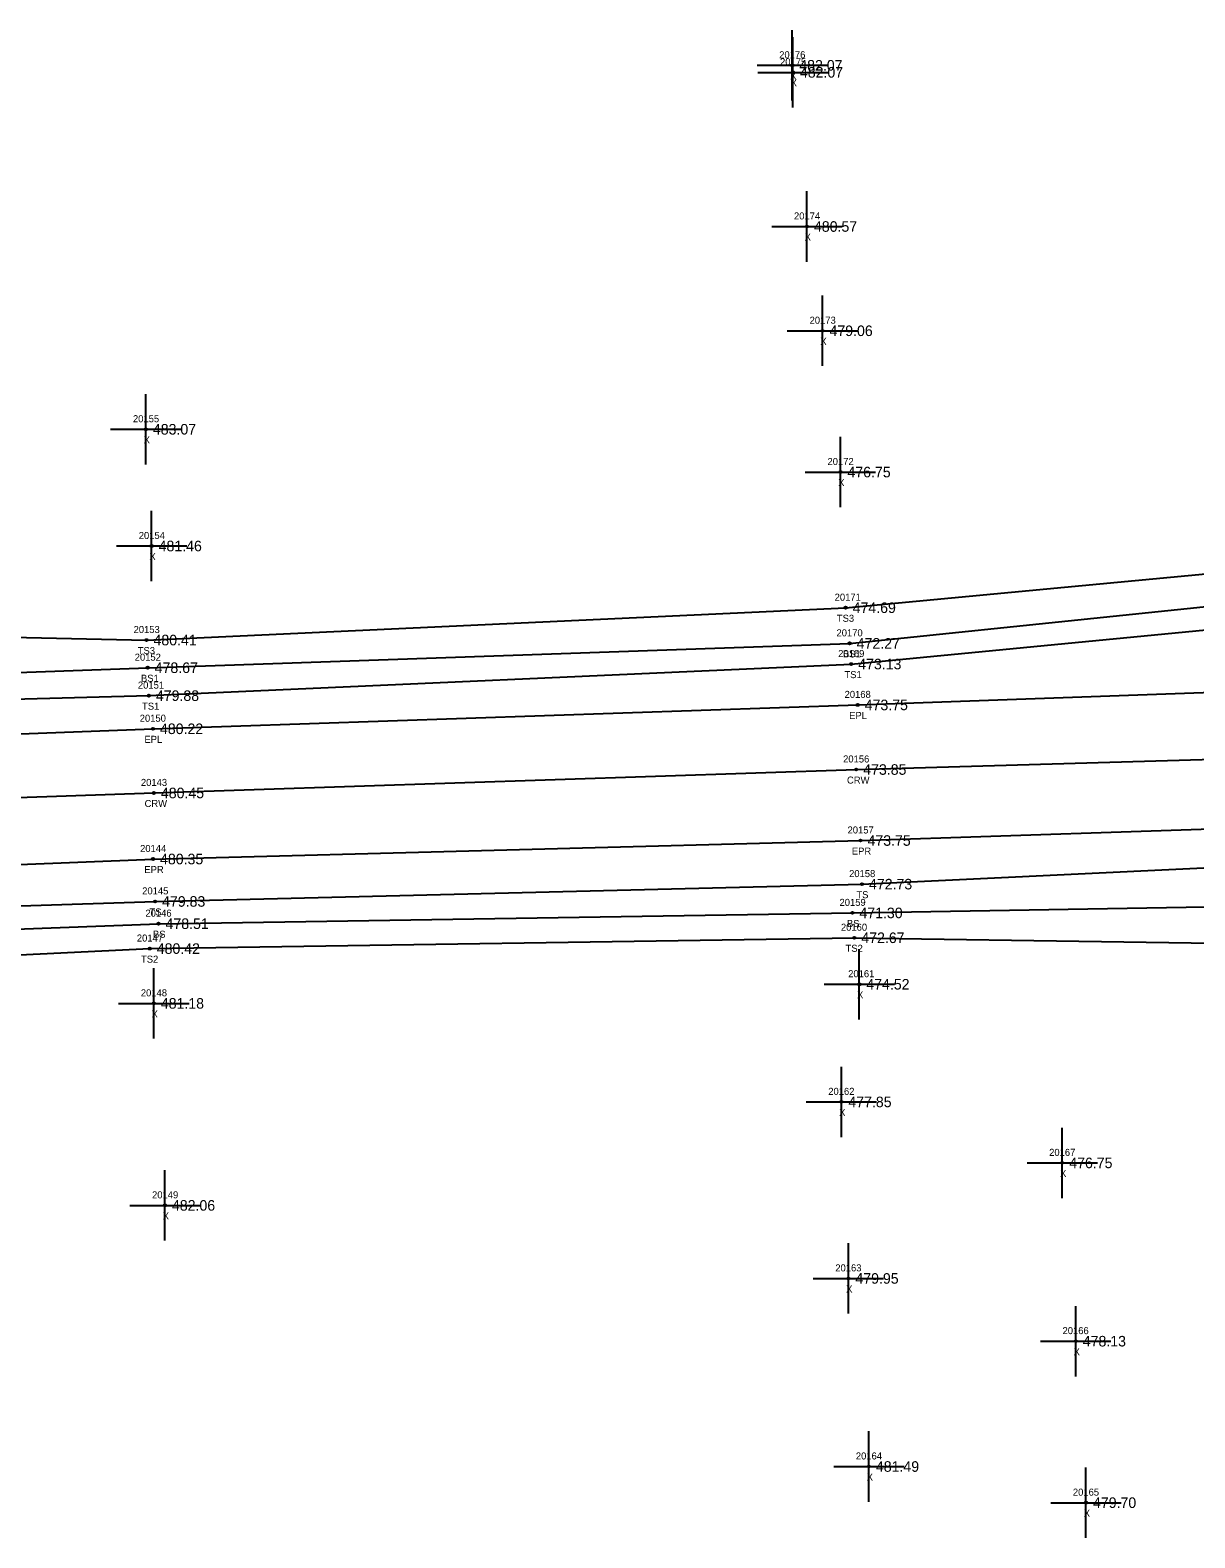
# Model space of a CAD drawing. Extents: x 1785066 to 1786589, y 770293 to 771312.
# Drawn here: x 1785562.6 to 1785728.1, y 770741.5 to 770955.7 of the extents above; entities that cross this region are included whole.
import ezdxf

# ---------------------------------------------------------------- set-up
doc = ezdxf.new("R2010")
doc.units = 0
for name, color, linetype in [('RD_DTM_BkLn1', 7, 'Continuous'), ('RD_DTM_BkLn2', 7, 'Continuous'), ('RD_DTM_BkLn_txCode', 7, 'Continuous'), ('RD_EX_Misc', 7, 'Continuous'), ('RD_EX_Misc_txCode', 7, 'Continuous'), ('RD_EX_Road', 7, 'Continuous'), ('RD_EX_Road_txCode', 7, 'Continuous'), ('RD_EX_TX_Misc_ELEV', 7, 'Continuous'), ('RD_EX_TX_Road_ELEV', 7, 'Continuous'), ('RD_HC_Survey_ELEV', 7, 'Continuous'), ('RD_HC_Survey_txCode', 7, 'Continuous'), ('RD_SMD_Locator', 7, 'Continuous')]:
    doc.layers.add(name, color=color, linetype=linetype)

msp = doc.modelspace()

# ---------------------------------------------------------------- linework, layer by layer
at = {"layer": 'RD_DTM_BkLn1'}
msp.add_lwpolyline([(1785082.06, 770851.29), (1785131.3, 770843.85), (1785181.17, 770839.05), (1785231.06, 770837.12), (1785280.99, 770837.06), (1785330.97, 770838.45), (1785380.81, 770840.43), (1785480.56, 770843.94), (1785580.22, 770847.33), (1785679.99, 770850.66), (1785779.91, 770853.54)], dxfattribs=at)
at = {"layer": 'RD_DTM_BkLn2'}
for points in [[(1785219, 770887.48), (1785221.61, 770869.17), (1785226.44, 770862.44), (1785230.83, 770863.64), (1785281.61, 770865.88), (1785330.18, 770866.95), (1785380.62, 770873.53), (1785481.03, 770871.22), (1785579.17, 770869.06), (1785678.49, 770873.66), (1785753.25, 770880.69), (1785777.57, 770887.66), (1785796.72, 770894.6)], [(1785221.18, 770856.06), (1785231.29, 770855.17), (1785280.9, 770855.5), (1785330.48, 770855.32), (1785380.39, 770857.59), (1785481.4, 770861.59), (1785579.34, 770865.13), (1785679.06, 770868.59), (1785753.94, 770876.35), (1785778.96, 770883.81)], [(1785221.33, 770857.68), (1785219.57, 770857.18), (1785219.95, 770853.94), (1785231.29, 770851.96), (1785280.92, 770852.98), (1785330.39, 770854.04), (1785380.75, 770854.37), (1785480.88, 770858.51), (1785579.51, 770861.16), (1785679.28, 770865.65), (1785754.2, 770872.9), (1785779.7, 770881.19), (1785786.95, 770881.8), (1785789.14, 770878.77), (1785786.05, 770869.32), (1785786.11, 770839.44)], [(1785205.07, 770819.03), (1785219.41, 770822.94), (1785230.95, 770822.33), (1785281.39, 770822.23), (1785331.37, 770822.34), (1785381.2, 770825.69), (1785481.76, 770828.75), (1785580.39, 770831.91), (1785680.81, 770834.37), (1785757.11, 770838.03), (1785775.28, 770836.8), (1785785.27, 770835.59), (1785786.11, 770839.44)], [(1785217.48, 770818.88), (1785230.53, 770818.92), (1785281.87, 770818.54), (1785331.33, 770820.31), (1785381.53, 770821.9), (1785481.77, 770825.03), (1785580.88, 770828.75), (1785679.45, 770830.28), (1785757.48, 770831.63), (1785774.02, 770829.34), (1785791.05, 770829.99), (1785795.95, 770830.77)], [(1785205.07, 770819.03), (1785218.74, 770813.87), (1785230.3, 770814.87), (1785282.58, 770814.55), (1785331.23, 770817.62), (1785381.61, 770819.76), (1785481.26, 770820.42), (1785579.63, 770825.21), (1785679.72, 770826.75), (1785756.33, 770825.6), (1785774.03, 770825.73), (1785791.3, 770827.72), (1785795.65, 770828.98)]]:
    msp.add_lwpolyline(points, dxfattribs=at)
at = {"layer": 'RD_EX_Misc'}
for p, q in [((1785670.91, 770945.75), (1785670.91, 770955.75)), ((1785671, 770944.75), (1785671, 770954.75)), ((1785665.91, 770950.75), (1785675.91, 770950.75)), ((1785666, 770949.75), (1785676, 770949.75)), ((1785672.99, 770922.84), (1785672.99, 770932.84)), ((1785667.99, 770927.84), (1785677.99, 770927.84)), ((1785675.2, 770908.02), (1785675.2, 770918.02)), ((1785670.2, 770913.02), (1785680.2, 770913.02)), ((1785579.08, 770894.02), (1785579.08, 770904.02)), ((1785574.08, 770899.02), (1785584.08, 770899.02)), ((1785677.75, 770887.94), (1785677.75, 770897.94)), ((1785672.75, 770892.94), (1785682.75, 770892.94)), ((1785579.9, 770877.43), (1785579.9, 770887.43)), ((1785574.9, 770882.43), (1785584.9, 770882.43)), ((1785680.43, 770815.14), (1785680.43, 770825.14)), ((1785580.21, 770812.42), (1785580.21, 770822.42)), ((1785675.43, 770820.14), (1785685.43, 770820.14)), ((1785575.21, 770817.42), (1785585.21, 770817.42)), ((1785677.88, 770798.42), (1785677.88, 770808.42)), ((1785672.88, 770803.42), (1785682.88, 770803.42)), ((1785709.26, 770789.75), (1785709.26, 770799.75)), ((1785581.79, 770783.71), (1785581.79, 770793.71)), ((1785704.26, 770794.75), (1785714.26, 770794.75)), ((1785576.79, 770788.71), (1785586.79, 770788.71)), ((1785678.88, 770773.33), (1785678.88, 770783.33)), ((1785673.88, 770778.33), (1785683.88, 770778.33)), ((1785711.18, 770764.41), (1785711.18, 770774.41)), ((1785706.18, 770769.41), (1785716.18, 770769.41)), ((1785681.79, 770746.6), (1785681.79, 770756.6)), ((1785676.79, 770751.6), (1785686.79, 770751.6)), ((1785712.63, 770741.46), (1785712.63, 770751.46)), ((1785707.63, 770746.46), (1785717.63, 770746.46))]:
    msp.add_line(p, q, dxfattribs=at)
at = {"layer": 'RD_EX_Road'}
for points in [[(1785083.87, 770860.72), (1785132.91, 770853.08), (1785181.89, 770848.53), (1785200.96, 770847.97), (1785215.21, 770848.13), (1785231.38, 770846.18), (1785281.19, 770846.16), (1785330.68, 770847.27), (1785380.41, 770849.82), (1785480.96, 770852.71), (1785580.09, 770856.45), (1785680.2, 770859.84), (1785779.71, 770863.4)], [(1785079.74, 770841.1), (1785077.36, 770829.81), (1785127.59, 770822.23), (1785177.27, 770813.99), (1785180.45, 770828), (1785230.74, 770826.87), (1785281.16, 770827.18), (1785331.14, 770828.42), (1785381.03, 770830.27), (1785481.34, 770833.99), (1785580.1, 770837.94), (1785680.6, 770840.57), (1785780.28, 770843.87)]]:
    msp.add_lwpolyline(points, dxfattribs=at)
at = {"layer": 'RD_SMD_Locator'}
for centre in [(1785670.91, 770950.75), (1785671, 770949.75), (1785672.99, 770927.84), (1785675.2, 770913.02), (1785579.08, 770899.02), (1785677.75, 770892.94), (1785579.9, 770882.43), (1785678.49, 770873.66), (1785579.17, 770869.06), (1785679.06, 770868.59), (1785579.34, 770865.13), (1785679.28, 770865.65), (1785579.51, 770861.16), (1785680.2, 770859.84), (1785580.09, 770856.45), (1785679.99, 770850.66), (1785580.22, 770847.33), (1785680.6, 770840.57), (1785580.1, 770837.94), (1785680.81, 770834.37), (1785580.39, 770831.91), (1785679.45, 770830.28), (1785580.88, 770828.75), (1785579.63, 770825.21), (1785679.72, 770826.75), (1785680.43, 770820.14), (1785580.21, 770817.42), (1785677.88, 770803.42), (1785709.26, 770794.75), (1785581.79, 770788.71), (1785678.88, 770778.33), (1785711.18, 770769.41), (1785681.79, 770751.6), (1785712.63, 770746.46)]:
    msp.add_circle(centre, 0.15, dxfattribs=at)

# ---------------------------------------------------------------- texts
at = {"layer": 'RD_DTM_BkLn_txCode'}
for s, p in [('20171', (1785676.93, 770874.66)), ('TS3', (1785677.24, 770871.66)), ('20153', (1785577.34, 770870.06)), ('20170', (1785677.19, 770869.59)), ('20152', (1785577.5, 770866.13)), ('TS3', (1785577.93, 770867.06)), ('20169', (1785677.43, 770866.65)), ('BS1', (1785678.12, 770866.59)), ('BS1', (1785578.39, 770863.13)), ('TS1', (1785678.32, 770863.65)), ('20151', (1785577.95, 770862.16)), ('TS1', (1785578.54, 770859.16)), ('20158', (1785678.98, 770835.37)), ('20145', (1785578.56, 770832.91)), ('20159', (1785677.62, 770831.28)), ('TS', (1785680.02, 770832.37)), ('20146', (1785579.02, 770829.75)), ('TS', (1785579.6, 770829.91)), ('BS', (1785580.1, 770826.75)), ('20160', (1785677.82, 770827.75)), ('BS', (1785678.67, 770828.28)), ('20147', (1785577.8, 770826.21)), ('TS2', (1785678.48, 770824.75)), ('TS2', (1785578.39, 770823.21))]:
    msp.add_text(s, height=1, dxfattribs=at).set_placement(p)
at = {"layer": 'RD_EX_Misc_txCode'}
for s, p in [('20176', (1785669.05, 770951.75)), ('20175', (1785669.17, 770950.75)), ('X', (1785670.6, 770948.75)), ('X', (1785670.69, 770947.75)), ('20174', (1785671.15, 770928.84)), ('X', (1785672.67, 770925.84)), ('20173', (1785673.37, 770914.02)), ('X', (1785674.89, 770911.02)), ('20155', (1785577.25, 770900.02)), ('X', (1785578.77, 770897.02)), ('20172', (1785675.91, 770893.94)), ('X', (1785677.43, 770890.94)), ('20154', (1785578.07, 770883.43)), ('X', (1785579.59, 770880.43)), ('20161', (1785678.85, 770821.14)), ('20148', (1785578.37, 770818.42)), ('X', (1785680.11, 770818.14)), ('X', (1785579.89, 770815.42)), ('20162', (1785676.02, 770804.42)), ('X', (1785677.57, 770801.42)), ('20167', (1785707.4, 770795.75)), ('X', (1785708.95, 770792.75)), ('20149', (1785579.96, 770789.71)), ('X', (1785581.48, 770786.71)), ('20163', (1785677.02, 770779.33)), ('X', (1785678.56, 770776.33)), ('20166', (1785709.3, 770770.41)), ('X', (1785710.87, 770767.41)), ('20164', (1785679.94, 770752.6)), ('X', (1785681.48, 770749.6)), ('20165', (1785710.77, 770747.46)), ('X', (1785712.32, 770744.46))]:
    msp.add_text(s, height=1, dxfattribs=at).set_placement(p)
at = {"layer": 'RD_EX_Road_txCode'}
for s, p in [('20168', (1785678.34, 770860.84)), ('20150', (1785578.21, 770857.45)), ('EPL', (1785678.99, 770857.84)), ('EPL', (1785578.88, 770854.45)), ('20157', (1785678.76, 770841.57)), ('20144', (1785578.26, 770838.94)), ('EPR', (1785679.37, 770838.57)), ('EPR', (1785578.87, 770835.94))]:
    msp.add_text(s, height=1, dxfattribs=at).set_placement(p)
at = {"layer": 'RD_EX_TX_Misc_ELEV'}
for s, p in [('482.07', (1785671.91, 770950)), ('482.07', (1785672, 770949)), ('480.57', (1785673.99, 770927.09)), ('479.06', (1785676.2, 770912.27)), ('483.07', (1785580.08, 770898.27)), ('476.75', (1785678.75, 770892.19)), ('481.46', (1785580.9, 770881.68)), ('474.69', (1785679.49, 770872.91)), ('480.41', (1785580.17, 770868.31)), ('472.27', (1785680.06, 770867.84)), ('473.13', (1785680.28, 770864.9)), ('478.67', (1785580.34, 770864.38)), ('479.88', (1785580.51, 770860.41)), ('472.73', (1785681.81, 770833.62)), ('479.83', (1785581.39, 770831.16)), ('471.30', (1785680.45, 770829.53)), ('478.51', (1785581.88, 770828)), ('472.67', (1785680.72, 770826)), ('480.42', (1785580.63, 770824.46)), ('474.52', (1785681.43, 770819.39)), ('481.18', (1785581.21, 770816.67)), ('477.85', (1785678.88, 770802.67)), ('476.75', (1785710.26, 770794)), ('482.06', (1785582.79, 770787.96)), ('479.95', (1785679.88, 770777.58)), ('478.13', (1785712.18, 770768.66)), ('481.49', (1785682.79, 770750.85)), ('479.70', (1785713.63, 770745.71))]:
    msp.add_text(s, height=1.5, dxfattribs=at).set_placement(p)
at = {"layer": 'RD_EX_TX_Road_ELEV'}
for s, p in [('473.75', (1785681.2, 770859.09)), ('480.22', (1785581.09, 770855.7)), ('473.75', (1785681.6, 770839.82)), ('480.35', (1785581.1, 770837.19))]:
    msp.add_text(s, height=1.5, dxfattribs=at).set_placement(p)
at = {"layer": 'RD_HC_Survey_ELEV'}
for s, p in [('473.85', (1785680.99, 770849.91)), ('480.45', (1785581.22, 770846.58))]:
    msp.add_text(s, height=1.5, dxfattribs=at).set_placement(p)
at = {"layer": 'RD_HC_Survey_txCode'}
for s, p in [('20156', (1785678.13, 770851.66)), ('20143', (1785578.38, 770848.33)), ('CRW', (1785678.68, 770848.66)), ('CRW', (1785578.9, 770845.33))]:
    msp.add_text(s, height=1, dxfattribs=at).set_placement(p)

doc.saveas('drawing.dxf')
